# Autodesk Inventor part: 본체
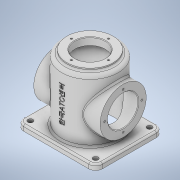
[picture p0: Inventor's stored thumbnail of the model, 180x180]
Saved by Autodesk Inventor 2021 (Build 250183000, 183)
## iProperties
Created: 2021-02
Part Number: 본체
Material: 알루미늄 6061
Document SubType Name: Modeling
Designer: 201-12
Density: 2.7 g/cm^3
Appearance: 기본값
Author: 201-12
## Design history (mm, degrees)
sketch "스케치1"
  geometry: L1 (-70, 60)-(70, 60); L2 (70, 60)-(70, -60); L3 (70, -60)-(-70, -60); L4 (-70, -60)-(-70, 60); L5 (-70, 60)-(70, -60); L6 (70, 60)-(-70, -60); 1 further point
  constraints: 12 end point, 2 midpoint, 2 parallel, 1 horizontal, 1 perpendicular
  dimensions: "d0" = 140 distance of L2.end L3.end; "d1" = 120 distance of L1.end L2.end
extrude "돌출1" new body sketch "스케치1" distance "d2" = 10; taper "d3" = 0 deg
sketch "스케치2"
  geometry: C1 r 50 at (0, 0); 1 further point
  constraints: 1 centre point, 1 coincident
  dimensions: "d4" = 100 diameter of C1
extrude "돌출2" join sketch "스케치2" distance "d5" = 110; taper "d6" = 0 deg
sketch "스케치3"
  geometry: C1 r 50 at (0, 0) reference; C2 r 41 at (0, 0); 1 further point
  constraints: 1 centre point, 1 coincident
  dimensions: "d7" = 82 diameter of C2
extrude "돌출3" join sketch "스케치3" distance "d8" = 5; taper "d9" = 0 deg
sketch "스케치4"
  geometry: L1 (0, 60)-(0, -60) reference; L2 (0, -60)-(0, 60) reference; C1 r 41 at (60, 0); 1 further point
  constraints: 1 centre point, 1 horizontal alignment
  dimensions: "d10" = 82 diameter of C1; "d11" = 60 distance of point (0, 0) C1.centre
extrude "돌출4" join sketch "스케치4" stored distance "d12" = 118; taper "d13" = 0 deg
sketch "스케치5"
  geometry: L1 (41, 125)-(-41, 125) reference; L2 (0, 125)-(-27, 125); L3 (-27, 125)-(-27, 112); L4 (-27, 112)-(0, 112); L5 (0, 112)-(0, 125); L6 (0, 112)-(-42, 112); L7 (-42, 112)-(-42, 0); L8 (-42, 0)-(0, 0); L9 (0, 0)-(0, 112); 3 further points
  constraints: 16 end point, 4 parallel, 2 horizontal, 2 perpendicular, 1 midpoint
  dimensions: "d14" = 27 distance between parallel lines of L5 L3; "d15" = 42 distance between parallel lines of L9 L7; "d16" = 13 distance between parallel lines of L1 L4; "d17" = 112 distance between parallel lines of L4 L8
revolve "회전1" sketch "스케치5" stored, may be unused: angle "d18" = 90 deg
sketch "스케치6"
  geometry: C1 r 41 at (0, 0) reference; C2 r 27 at (0, 0); 1 further point
  constraints: 1 centre point, 1 coincident
  dimensions: "d19" = 54 diameter of C2
extrude "돌출5" cut sketch "스케치6" stored distance "d20" = 0; taper "d21" = 0 deg
sketch "스케치7"
  geometry: L1 (-33, 0)-(33, 0); L2 (0, 33)-(0, -33); C1 r 41 at (0, 0) reference; A1 r 33 centre (0, 0) between (-33, 0) and (33, 0); 7 further points
  constraints: 5 coincident, 4 end point, 4 midpoint, 4 point on circle, 1 centre point, 1 horizontal, 1 vertical
  dimensions: "d22" = 66 diameter of A1
hole "구멍1" sketch "스케치7" at (0, 33), (-33, 0), (33, 0), (0, -33) diameter "d23" = 3.242; stored, may be unused: countersink angle "d27" = 90 deg, drill point angle "d29" = 118 deg; dims "d24" = 8, "d25" = 4, "d26" = 2, "d28" = 10
sketch "스케치8"
  geometry: L1 (-33, 0)-(33, 0); L2 (0, 33)-(0, -33); C1 r 41 at (0, 0) reference; A1 r 33 centre (0, 0) between (-33, 0) and (33, 0); 7 further points
  constraints: 5 coincident, 4 end point, 4 midpoint, 4 point on circle, 1 centre point, 1 horizontal, 1 vertical
  dimensions: "d30" = 66 diameter of A1
hole "구멍2" sketch "스케치8" at (0, 33), (-33, 0), (0, -33), (33, 0) diameter "d31" = 3.242; stored, may be unused: countersink angle "d35" = 90 deg, drill point angle "d37" = 118 deg; dims "d32" = 8, "d33" = 4, "d34" = 2, "d36" = 10
fillet "모깎기1" dims "d38" = 12
sketch "스케치9"
  geometry: L1 (-58, -60)-(58, -60) reference; L2 (70, -48)-(70, 48) reference; L3 (58, 60)-(-58, 60) reference; L4 (-70, 48)-(-70, -48) reference; C1 r 50 at (0, 0) reference; A1 r 12 centre (-58, -48) between (-70, -48) and (-58, -60) reference; A2 r 12 centre (58, -48) between (58, -60) and (70, -48) reference; A3 r 12 centre (58, 48) between (70, 48) and (58, 60) reference; A4 r 12 centre (-58, 48) between (-58, 60) and (-70, 48) reference; 5 further points
  constraints: 4 coincident
hole "구멍3" sketch "스케치9" at (58, -48), (-58, -48), (-58, 48), (58, 48) diameter "d39" = 9; stored, may be unused: countersink angle "d43" = 90 deg, drill point angle "d45" = 0 deg; dims "d40" = 8, "d41" = 4, "d42" = 2, "d44" = 10
fillet "모깎기2" dims "d46" = 3
chamfer "모따기1" distance "d47" = 1; stored, may be unused: second distance "d48" = 2, angle "d49" = 45 deg
chamfer "모따기2" distance "d50" = 1; stored, may be unused: second distance "d51" = 2, angle "d52" = 45 deg
fillet "모깎기3" dims "d53" = 3
chamfer "모따기3" distance "d54" = 1; stored, may be unused: second distance "d55" = 2, angle "d56" = 45 deg
fillet "모깎기4" dims "d57" = 6
fillet "모깎기5" dims "d58" = 3
node "작업 평면1"
sketch "스케치10"
  geometry: L1 (-58, 0)-(58, 0) reference; 3 further points
  constraints: 1 midpoint, 1 vertical alignment, 1 other
  dimensions: "d62" = 66 distance of point (0, 66) point (0, 0)
feature "엠보싱1" sketch "스케치10" dims "d0" = 140, "d1" = 120, "d60" = 0.5, "d61" = 0
node "솔리드1"
mirror "미러1"
node "투영된 루프1"
node "투영된 루프2"
node "투영된 루프3"
feature "A9D066F2-1C7D-4E18-AEED-F7BC21143FA4" dims "d31" = 3.242, "d32" = 8, "d33" = 4, "d34" = 2, "d35" = 90 deg, "d36" = 10, "d37" = 118 deg
other parameters: "d59" = 104
